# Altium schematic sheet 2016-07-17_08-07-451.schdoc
size 236 x 218 mm; SheetNumber: 1; SheetTotal: 1
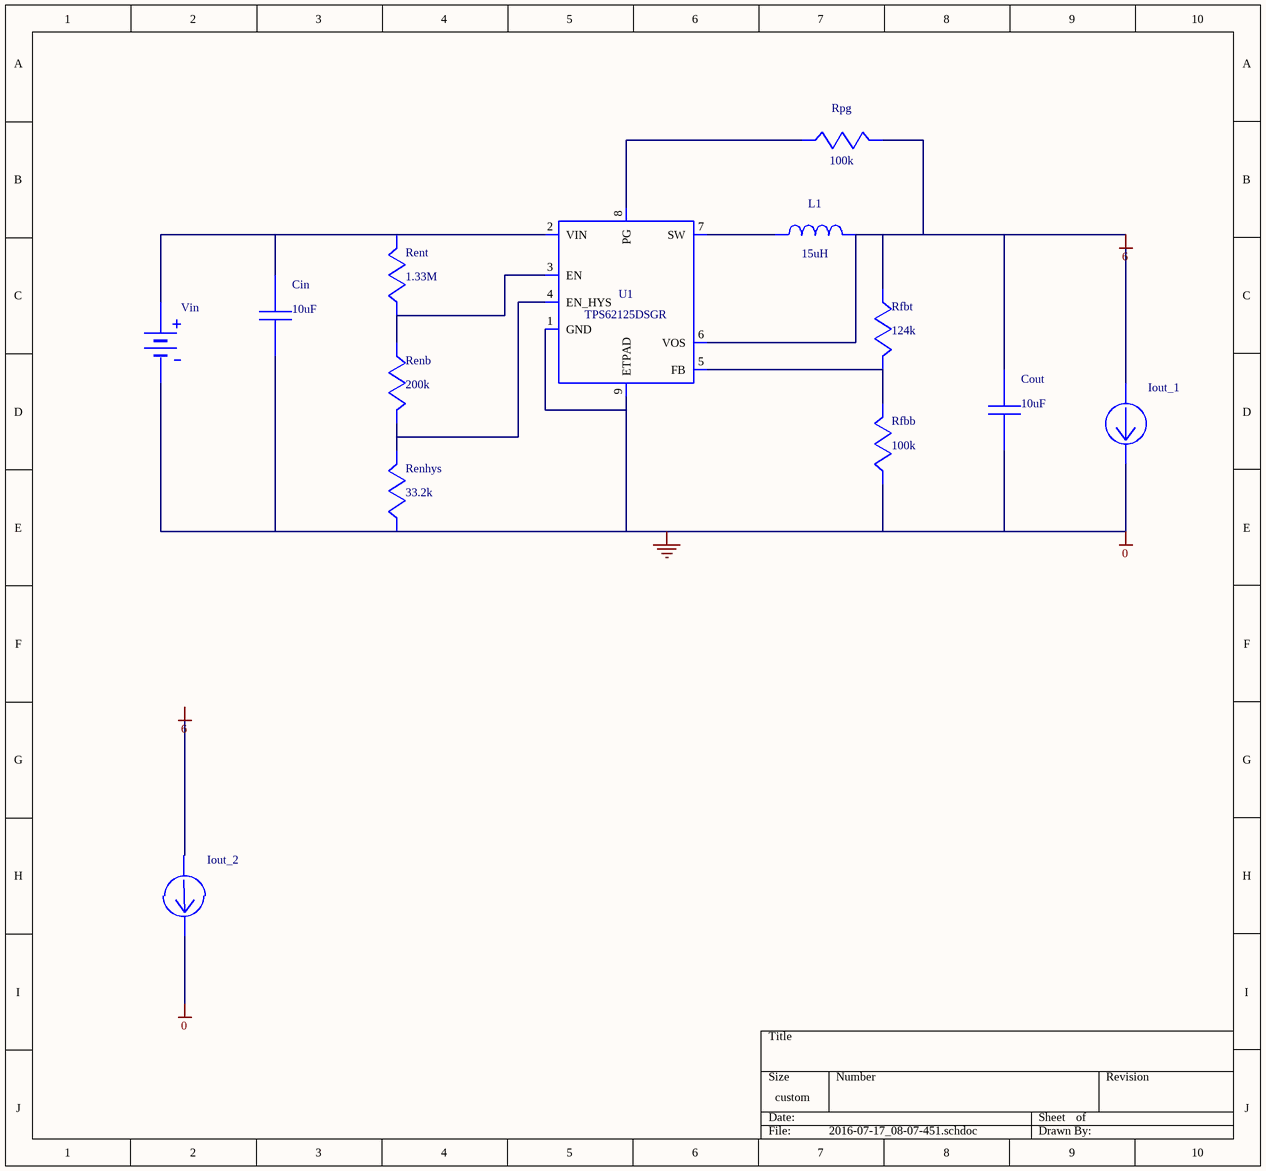
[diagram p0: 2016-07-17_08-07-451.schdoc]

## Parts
Cin  value 10uF  (hidden comment: GRM21BR61C106KE15L)
Cout  value 10uF  (hidden comment: GRM188R60G106ME47D)
Iout_1  WB_CURRENT_LOAD  (value not drawn)
Iout_2  WB_CURRENT_LOAD  (value not drawn)
L1  value 15uH  (hidden comment: NPI43C150MTRF)
Renb  value 200k  (hidden comment: CRCW0402200KFKED)
Renhys  value 33.2k  (hidden comment: CRCW040233K2FKED)
Rent  value 1.33M  (hidden comment: CRCW04021M33FKED)
Rfbb  value 100k  (hidden comment: CRCW0402100KFKED)
Rfbt  value 124k  (hidden comment: CRCW0402124KFKED)
Rpg  value 100k  (hidden comment: CRCW0402100KFKED)
U1  TPS62125DSGT  (value not drawn)
Vin  WB_BATTERY  (value not drawn)

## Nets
0: Cin.2 Cout.2 Iout_1.2(-) Iout_2.2(-) Renhys.2 Rfbb.2 U1.1(GND) U1.9(ETPAD) Vin.2(-)
6: Cout.1 Iout_1.1(+) L1.1 Rfbt.2 Rpg.1 U1.6(VOS)
NetCin_1: Cin.1 Rent.1 U1.2(VIN) Vin.1(+)
NetL1_2: L1.2 U1.7(SW)
NetRenb_1: Renb.1 Renhys.1 U1.4(EN_HYS)
NetRenb_2: Renb.2 Rent.2 U1.3(EN)
NetRfbb_1: Rfbb.1 Rfbt.1 U1.5(FB)
NetRpg_2: Rpg.2 U1.8(PG)

Not connected (* = marked no-connect by the designer): Iout_2 1(+)

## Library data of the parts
Cin = GRM21BR61C106KE15L: GRM21BR61C106KE1; Manufacturer Name: MuRata
Cout = GRM188R60G106ME47D: GRM188R60G106ME4; Manufacturer Name: MuRata
L1 = NPI43C150MTRF: Manufacturer Name: NIC Components
Renb = CRCW0402200KFKED: Manufacturer Name: Vishay-Dale
Renhys = CRCW040233K2FKED: Manufacturer Name: Vishay-Dale
Rent = CRCW04021M33FKED: Manufacturer Name: Vishay-Dale
Rfbb Rpg = CRCW0402100KFKED: Manufacturer Name: Vishay-Dale
Rfbt = CRCW0402124KFKED: Manufacturer Name: Vishay-Dale
U1 = TPS62125DSGT: TPS62125DSGR; Manufacturer Name: Texas Instruments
